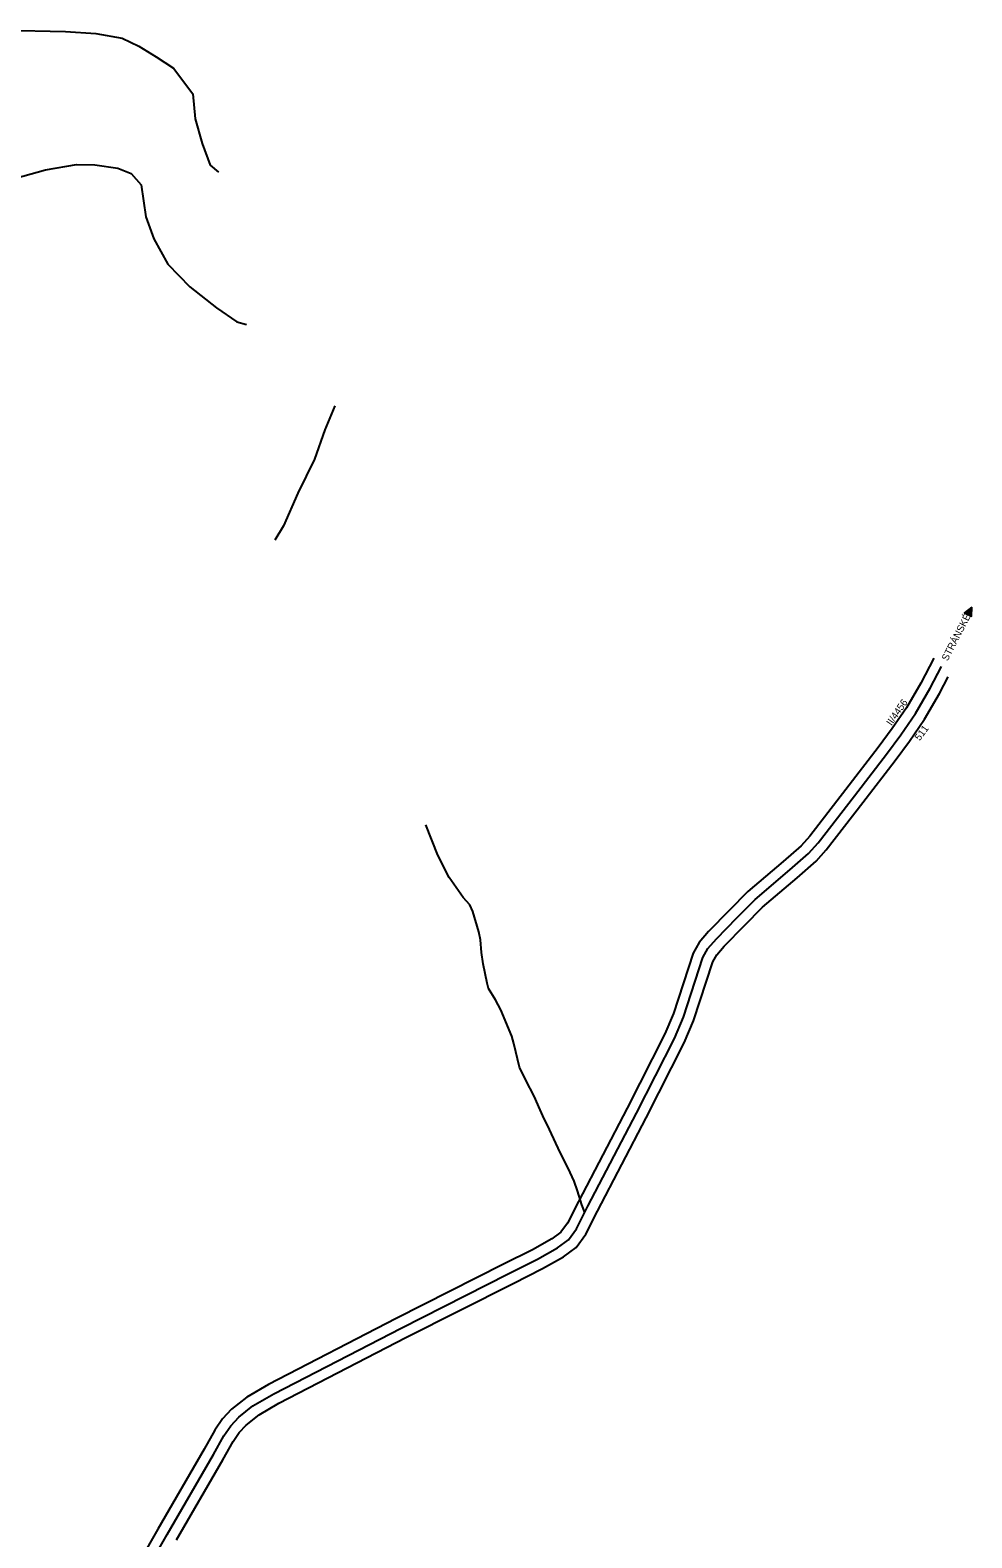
# Model space of a CAD drawing. Extents: x -547395 to -536032, y -1096268 to -1086572.
# Drawn here: x -542676 to -541353, y -1092255 to -1090136 of the extents above; entities that cross this region are included whole.
import ezdxf

# ---------------------------------------------------------------- set-up
doc = ezdxf.new("R2010")
doc.units = 0
for name, color, linetype in [('Vrstva 12', 7, 'Continuous'), ('Vrstva 66', 7, 'Continuous'), ('Vrstva 7', 7, 'Continuous'), ('Vrstva 73', 7, 'Continuous')]:
    doc.layers.add(name, color=color, linetype=linetype)

msp = doc.modelspace()

# ---------------------------------------------------------------- linework, layer by layer
at = {"layer": 'Vrstva 12'}
for points in [[(-542711.5, -1090136), (-542625.8, -1090138.1), (-542583.4, -1090140.5), (-542546.4, -1090147.1), (-542523.1, -1090158.4), (-542498.6, -1090173.4), (-542474.1, -1090189.5), (-542447.2, -1090225.4), (-542443.6, -1090260.6), (-542434.1, -1090295.3), (-542422.7, -1090325.8), (-542411.2, -1090335.6)], [(-542718.1, -1090350.2), (-542654.2, -1090332.2), (-542610.7, -1090325), (-542584.9, -1090325.4), (-542552.3, -1090330.1), (-542533.6, -1090337.3), (-542519.6, -1090353.3), (-542513.2, -1090398.2), (-542502, -1090429.1), (-542482, -1090464.8), (-542451.4, -1090496.8), (-542413.6, -1090526.4), (-542385, -1090545.9), (-542371.5, -1090549.7)], [(-542247.7, -1090664), (-542261.4, -1090697.7), (-542276.3, -1090738.8), (-542299.5, -1090786.4), (-542319.7, -1090832.3), (-542331.6, -1090852.5)], [(-541896.3, -1091797.4), (-541900.4, -1091786.5), (-541906.4, -1091766.9), (-541911.4, -1091753.2), (-541919.8, -1091735), (-541931.1, -1091713.3), (-541945.8, -1091680.7), (-541955.3, -1091661.6), (-541959.2, -1091653.1), (-541967.4, -1091634.2), (-541979.4, -1091611.6), (-541988, -1091593.1), (-541995.9, -1091560), (-541998.9, -1091549.6), (-542014.1, -1091512.6), (-542021.8, -1091498.7), (-542031.6, -1091482.9), (-542033.7, -1091475.4), (-542039.3, -1091447.8), (-542041.3, -1091432.1), (-542042.8, -1091414.3), (-542045.4, -1091403.2), (-542053.8, -1091374.7), (-542057.9, -1091365.1), (-542067.2, -1091355), (-542086.8, -1091326.9), (-542102.7, -1091295.2), (-542119.5, -1091252.8)]]:
    msp.add_lwpolyline(points, dxfattribs=at)
at = {"layer": 'Vrstva 66'}
for points in [[(-541406, -1091018.3), (-541424.2, -1091053.6), (-541444.4, -1091088.4), (-541464.4, -1091117.4), (-541484.4, -1091144.2), (-541529.4, -1091202.9), (-541580.2, -1091268.5), (-541592.6, -1091282.3), (-541617.9, -1091304.4), (-541667.1, -1091346.4), (-541693.4, -1091373), (-541722.4, -1091402.7), (-541735.6, -1091417.8), (-541744.2, -1091433), (-541771.8, -1091517.7), (-541783.9, -1091546.4), (-541836.8, -1091650.9), (-541905.2, -1091781.8), (-541920.8, -1091812.4), (-541930, -1091825), (-541942.9, -1091834.4), (-541969.7, -1091849.9), (-542010.7, -1091870.2), (-542161.2, -1091946.5), (-542340.7, -1092038.9), (-542371.1, -1092056.9), (-542392.6, -1092074), (-542405.5, -1092087.6), (-542416.1, -1092103.4), (-542431.2, -1092130), (-542496, -1092242.5), (-542547.6, -1092332.9)], [(-542470, -1092257.4), (-542405.1, -1092144.9), (-542390.5, -1092119.2), (-542382, -1092106.4), (-542372.3, -1092096.2), (-542354, -1092081.7), (-542326.1, -1092065.2), (-542147.6, -1091973.2), (-541997.2, -1091897), (-541955.6, -1091876.3), (-541926.5, -1091859.6), (-541908.5, -1091846.5), (-541895.1, -1091828.1), (-541878.5, -1091795.6), (-541810.1, -1091664.6), (-541756.6, -1091559), (-541743.7, -1091528.2), (-541716.6, -1091445.2), (-541711, -1091435.3), (-541700.4, -1091423), (-541672, -1091394.1), (-541646.6, -1091368.4), (-541598.2, -1091327.1), (-541571.5, -1091303.6), (-541557.1, -1091287.7), (-541505.6, -1091221.2), (-541460.5, -1091162.3), (-541440.1, -1091134.9), (-541419.1, -1091104.4), (-541397.9, -1091068), (-541385.8, -1091044.6)]]:
    msp.add_lwpolyline(points, dxfattribs=at)
at = {"layer": 'Vrstva 7'}
for points in [[(-541352.6, -1090946.8), (-541362.9, -1090954.6), (-541352.9, -1090959.7)], [(-541353.4, -1090948.4), (-541361.4, -1090954.4), (-541353.7, -1090958.4)], [(-541354.3, -1090950.1), (-541359.9, -1090954.3), (-541354.4, -1090957.1)], [(-541355.1, -1090951.7), (-541358.4, -1090954.2), (-541355.2, -1090955.8)], [(-541355.9, -1090953.3), (-541356.9, -1090954), (-541356, -1090954.5)]]:
    msp.add_lwpolyline(points, close=True, dxfattribs=at)
msp.add_lwpolyline([(-542534.4, -1092340.1), (-542483, -1092249.9), (-542418.2, -1092137.5), (-542403.3, -1092111.3), (-542393.8, -1092097), (-542382.5, -1092085.1), (-542362.6, -1092069.3), (-542333.4, -1092052.1), (-542154.4, -1091959.8), (-542004, -1091883.6), (-541962.6, -1091863.1), (-541934.7, -1091847), (-541919.2, -1091835.7), (-541907.9, -1091820.2), (-541891.9, -1091788.7), (-541823.5, -1091657.8), (-541770.3, -1091552.7), (-541757.8, -1091523), (-541730.4, -1091439.1), (-541723.3, -1091426.6), (-541711.4, -1091412.9), (-541682.7, -1091383.6), (-541656.8, -1091357.4), (-541608.1, -1091315.7), (-541582.1, -1091292.9), (-541568.7, -1091278.1), (-541517.5, -1091212), (-541472.5, -1091153.2), (-541452.3, -1091126.2), (-541431.7, -1091096.4), (-541411.1, -1091060.8), (-541395.8, -1091031.3)], dxfattribs=at)
at = {"layer": 'Vrstva 73'}
msp.add_lwpolyline([(-542534.4, -1092340.1), (-542483, -1092249.9), (-542418.2, -1092137.5), (-542403.3, -1092111.3), (-542393.8, -1092097), (-542382.5, -1092085.1), (-542362.6, -1092069.3), (-542333.4, -1092052.1), (-542154.4, -1091959.8), (-542004, -1091883.6), (-541962.6, -1091863.1), (-541934.7, -1091847), (-541919.2, -1091835.7), (-541907.9, -1091820.2), (-541891.9, -1091788.7), (-541823.5, -1091657.8), (-541770.3, -1091552.7), (-541757.8, -1091523), (-541730.4, -1091439.1), (-541723.3, -1091426.6), (-541711.4, -1091412.9), (-541682.7, -1091383.6), (-541656.8, -1091357.4), (-541608.1, -1091315.7), (-541582.1, -1091292.9), (-541568.7, -1091278.1), (-541517.5, -1091212), (-541472.5, -1091153.2), (-541452.3, -1091126.2), (-541431.7, -1091096.4), (-541411.1, -1091060.8), (-541395.4, -1091030.4)], dxfattribs=at)

# ---------------------------------------------------------------- texts
at = {"layer": 'Vrstva 7'}
for s, rotation, p in [('STRÁNSKÉ', 62.719, (-541386.8, -1091023.3)), ('II/4456', 55.4131, (-541465.4, -1091114.2))]:
    msp.add_text(s, height=10, rotation=rotation, dxfattribs=at).set_placement(p)
at = {"layer": 'Vrstva 73'}
msp.add_text('511', height=10, rotation=53.6308, dxfattribs=at).set_placement((-541425.8, -1091135.3))

doc.saveas('drawing.dxf')
